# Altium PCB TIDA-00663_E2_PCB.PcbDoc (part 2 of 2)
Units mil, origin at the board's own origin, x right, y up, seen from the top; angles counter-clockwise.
Board outline 1968.5 x 1968.5 mil, 4 copper layers (Top Layer, Mid-Layer 1, Mid-Layer 2, Bottom Layer), stack 90 mil thick; 73 components, 52 nets, 290 pads, 111 vias.
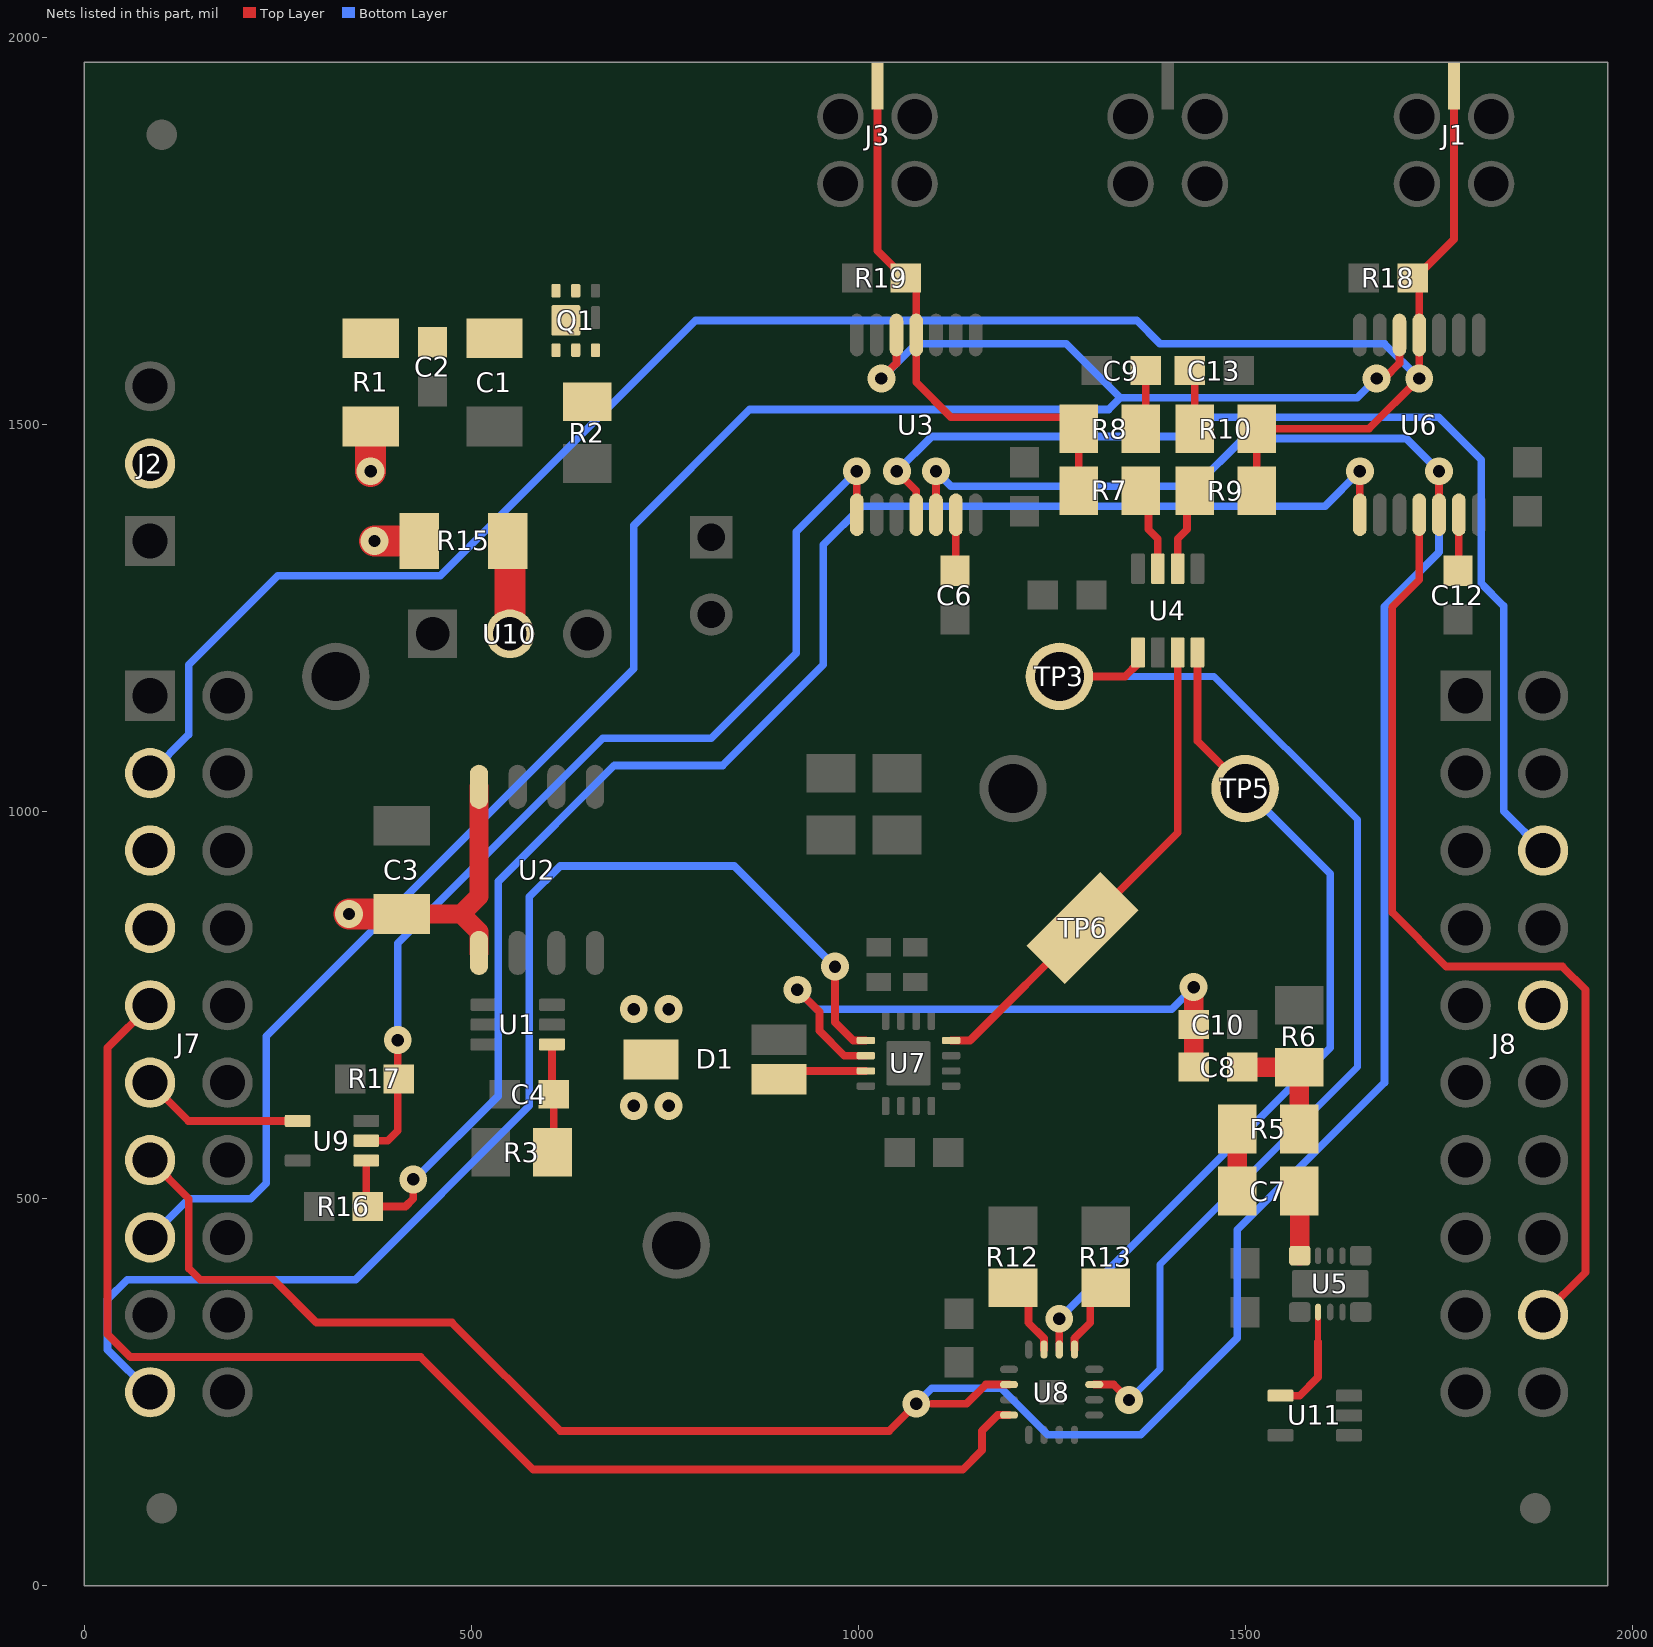
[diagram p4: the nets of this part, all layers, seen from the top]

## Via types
v1: diameter 36, hole 16, Top Layer to Bottom Layer, tented both sides, 84 vias
v2: diameter 19.68, hole 7.87, Top Layer to Bottom Layer, 25 vias
v3: diameter 19.68, hole 7.87, Top Layer to Bottom Layer, tented top, 1 vias
v4: diameter 36, hole 16, Top Layer to Bottom Layer, 1 vias

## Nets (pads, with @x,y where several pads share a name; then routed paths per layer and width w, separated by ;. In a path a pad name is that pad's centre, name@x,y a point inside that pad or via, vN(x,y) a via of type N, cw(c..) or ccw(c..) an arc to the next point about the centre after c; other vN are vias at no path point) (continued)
LASER_ON_THRESHOLD: TP3.1 U4.1 U8.11 | length 1469.7
  Top Layer w10: TP3.1@1300,1175 1345,1175 1361.61,1191.61 U4.1@1361.61,1205.87 ; U8.11@1305.12,259.84 1330.16,259.84 v1(1350,240)
  Bottom Layer w9: TP3.1@1260,1175 1460,1175 1645,990 1645,670 1390,415 1390,280 v1(1350,240)
NetC1_1: C1.1 C2.1 Q1.1 Q1.2 Q1.5 Q1.6 Q1.8 R1.1
NetC4_1: C4.1 R3.2 U1.1 | length 140.9
  Top Layer w10: C4.1@604.29,637.2 U1.1@604.29,699.41 ; R3.2@605,560 606.5,561.5 C4.1@606.5,635
  Top Layer w15: C4.1@604.29,637.2 C4.1@606.5,635
NetC6_1: C6.1 U3.13 | length 77.9
  Top Layer w10: C6.1@1125,1311.5 C6.1@1126.18,1312.68 ; C6.1@1126.18,1307.68 C6.1@1126.18,1312.68 ; U3.13@1126.18,1383.86 C6.1@1126.18,1312.68
NetC7_1: C7.1 R5.1 | length 80
  Top Layer w25: C7.1@1490,510 R5.1@1490,590
NetC7_2: C7.2 U5.13 U5.14 | length 83.8
  Top Layer w25: C7.2@1570,510 1570.63,509.37 U5.13@1570.63,426.42
NetC8_1: C8.1 R5.2 R6.1 | length 153.5
  Top Layer w25: C8.1@1496.5,670 R6.1@1570,670 R5.2@1570,590
NetC9_1: C9.1 R8.1 | length 77.7
  Top Layer w10: R8.1@1365,1495 1371.5,1501.5 C9.1@1371.5,1570
NetC12_1: C12.1 U6.13 | length 74.5
  Top Layer w10: C12.1@1775,1301.5 C12.1@1776.18,1302.68 ; C12.1@1775,1311.5 1776.18,1312.68 U6.13@1776.18,1383.86
NetC13_1: C13.1 R10.1 | length 77.7
  Top Layer w10: C13.1@1428.5,1570 1435,1563.5 R10.1@1435,1495
NetD1_3: D1.3 U7.15 | length 117.5
  Top Layer w10: D1.3@892.68,654.41 D1.3@893.43,655.16 ; D1.3@893.43,665.16 U7.15@1009.88,665.16
NetQ1_3: Q1.3 R2.2
NetR12_1: R12.1 U8.15 | length 96.5
  Top Layer w9: R12.1@1200,385 R12.1@1220,365
  Top Layer w10: R12.1@1220,365 1220,340 1240.16,319.84 U8.15@1240.16,305.12
NetR13_1: R13.1 U8.13 | length 96.6
  Top Layer w9: R13.1@1300,365 R13.1@1320,385
  Top Layer w10: U8.13@1279.53,305.12 1279.53,319.53 1300,340 R13.1@1300,365
NetR15_1: R15.1 U10.2 | length 121.2
  Top Layer w40: R15.1@547.09,1350 550,1347.09 U10.2@550,1230
NetTP6_1: TP6.1 U4.3 U7.8 | length 636.9
  Top Layer w10: U7.8@1120.12,704.53 1144.53,704.53 TP6.1@1290,850 1412.8,972.8 U4.3@1412.8,1205.87
NetU5_3: U5.3 U11.4 | length 142.6
  Top Layer w7.8: 1594.25,315 U5.3@1594.25,353.58
  Top Layer w10: U11.4@1545.71,245.59 1570.51,245.59 1594.25,269.33 1594.25,315
OPA_TEST_INPUT: C8.2 C10.1 U7.14 | length 777.2
  Top Layer w10: v1@923,770 v1(921.5,770) 950,741.5 950,717 982.16,684.84 U7.14@1009.88,684.84
  Top Layer w25: C8.2@1433.5,670 C10.1@1433.5,725 v1(1433.5,773.5)
  Bottom Layer w10: v1(921.5,770) 946.5,745 1405,745 v1(1433.5,773.5)
RST: J8.10
RX: J1.1 J7.3 R9.2 R10.2 R18.2 U6.4 | length 2679.2
  Top Layer w10: R9.2@1515,1415 R10.2@1515,1495 1660,1495 v1(1725,1560) U6.4@1725,1616.14 1725,1695 1770,1740 J1.1@1770,1937.5
  Bottom Layer w10: J7.3@85,1050 135,1100 135,1190 250,1305 460,1305 790,1635 1360,1635 1390,1605 1680,1605 v1(1725,1560)
RX_COMP: R9.1 U4.6 | length 110.1
  Top Layer w10: U4.6@1412.8,1314.13 1412.8,1352.8 1425,1365 1425,1405 R9.1@1435,1415
SPI_CLK_P1.3_BP7: J7.13 U3.12 U6.12 U8.2 | length 3853.7
  Top Layer w10: J7.13@85,550 135,500 135,410 149.65,395.35 244.65,395.35 300,340 475,340 615,200 1040,200 v1(1075,235) ; 1095,235 1140,235 1164.84,259.84 U8.2@1194.88,259.84 ; U3.12@1100.59,1383.86 v1(1100.59,1440) ; U6.12@1750.59,1383.86 v1(1750.59,1440)
  Bottom Layer w10: v1(1075,235) 1095,255 1185,255 1245,195 1365,195 1490,320 1490,460 1680,650 1680,1265 1750.59,1335.59 v1(1750.59,1440) 1708.22,1482.37 1497.37,1482.37 1435.62,1420.62 1119.97,1420.62 v1(1100.59,1440)
TDC_CLK: J7.15 U3.5 U6.5 | length 2759.1
  Top Layer w10: v1(1030,1560) 1049.41,1579.41 U3.5@1049.41,1616.14 ; v1(1670,1560) 1680,1560 1699.41,1579.41 U6.5@1699.41,1616.14
  Bottom Layer w10: J7.15@85,450 135,500 215,500 235,520 235,710 710,1185 710,1370 860,1520 1323.66,1520 1338.66,1535 ; v1(1030,1560) 1075,1605 1268.66,1605 1338.66,1535 ; v1(1670,1560) 1645,1535 1338.66,1535
TDC_INT: J7.11 U9.4 | length 221.2
  Top Layer w10: J7.11@85,650 134.41,600.59 U9.4@275.71,600.59 U9.4@285.71,600.59
TDC_RX_CS: J8.18 U6.11 | length 1262.6
  Top Layer w10: U6.11@1725,1383.86 1725,1300 1690,1265 1690,870 1760,800 1910,800 1940,770 1940,405 J8.18@1885,350
TDC_RX_INT: R16.1 U6.8 U9.1 | length 2059.5
  Top Layer w10: U9.1@364.29,549.41 364.29,492.2 R16.1@366.5,490 415,490 425,500 v1(425,525) ; U6.8@1648.23,1383.86 v1(1648.23,1440)
  Bottom Layer w10: v1(425,525) 427.17,525 535,632.83 535,910 685,1060 825,1060 955,1190 955,1345 1005,1395 1603.23,1395 v1(1648.23,1440)
TDC_TX_CS: J8.6 U3.11 | length 1411.4
  Top Layer w10: v1(1050,1440) 1075,1415 U3.11@1075,1383.86
  Bottom Layer w10: v1(1050,1440) 1095,1485 1415,1485 1440,1510 1750,1510 1805,1455 1805,1295 1834.13,1265.87 1834.13,1000.87 J8.6@1885,950
TDC_TX_INT: R17.1 U3.8 U9.2 | length 1287.7
  Top Layer w10: U9.2@364.29,575 391.91,575 405,588.09 v1(405,705) ; U3.8@998.23,1383.86 v1(998.23,1440)
  Bottom Layer w10: v1(405,705) 405,830 670,1095 810,1095 920,1205 920,1361.77 v1(998.23,1440) ; v1@994.11,1444.11 v1@998.23,1448.23
TPL0202_CS_EN_GPIO_BP5: J7.9 U8.4 | length 1729
  Top Layer w10: J7.9@85,750 30,695 30,325 59.65,295.35 434.65,295.35 580,150 1135,150 1160,175 1160,200 1180.47,220.47 U8.4@1194.88,220.47
TPROP_CALIBRATION_ENABLE_BP10_P3.6: J7.19 U7.13 | length 1648.4
  Top Layer w10: v1(970,800) 970,728 993.47,704.53 U7.13@1009.88,704.53
  Bottom Layer w10: J7.19@85,250 30,305 30,370 55.35,395.35 350.35,395.35 575,620 575,890 615,930 840,930 v1(970,800)
TX: J3.1 R7.2 R8.2 R19.2 U3.4 | length 718.1
  Top Layer w10: J3.1@1025,1937.5 1025,1725 1075,1675 U3.4@1075,1616.14 1075,1555 1120,1510 1270,1510 R8.2@1285,1495 R7.2@1285,1415
TX_COMP: R7.1 U4.7 | length 115.9
  Top Layer w10: R7.1@1365,1415 1375,1415 1375,1365 1387.2,1352.8 U4.7@1387.2,1314.13
UCA0RXD_P1.2_BP4: J7.7
UCA0TXD_P1.1_BP3: J7.5
VCC_LASER: C3.1 D1.1 J2.2 R1.2 R15.2 U2.1 U2.8 | length 494.4
  Top Layer w25: C3.1@410,867.91 487.09,867.91 ; U2.1@510,817.72 510,845 487.09,867.91 ; U2.8@510,1032.28 510,890.83 487.09,867.91
  Top Layer w40: v1(342.09,867.91) C3.1@410,867.91 ; v1(370,1440) R1.2@370,1497.91 ; v1(375,1350) R15.2@432.91,1350
  other v1: 710,620 755,620 710,745 755,745
VOUTN_DIGITAL: TP5.1 U4.4 U8.14 | length 1116.9
  Top Layer w10: U8.14@1259.84,305.12 v1(1259.84,344.84) ; U4.4@1438.39,1205.87 1438.39,1091.61 TP5.1@1500,1030
  Bottom Layer w10: v1(1259.84,344.84) 1610,695 1610,920 TP5.1@1500,1030
pads on no net: D1.2 FID1.1 FID2.1 FID3.1 J7.6 J7.8 J7.10 J7.12 J7.14 J7.16 J7.18 J7.20 J8.1 J8.3 J8.5 J8.7 J8.9 J8.11 J8.13 J8.15 J8.17 J8.19 U3.2 U3.6 U5.0 U5.1@1578.5,353.58 U5.1@1578.5,426.42 U5.1@1641.5,353.58 U5.1@1641.5,426.42 U5.2@1570.63,360.47 U5.2@1570.63,419.53 U5.2@1649.37,360.47 U5.2@1649.37,419.53 U5.6 U5.7 U5.8 U5.9 U5.10 U5.12 U6.2 U6.6 U7.5 U7.16 U8.5 U8.6 U8.8 U8.9 U8.16

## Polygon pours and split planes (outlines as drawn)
GND on Top Layer "Top Layer-No Net 1" (solid, remove dead copper, pour order 6): 1090,995 885,995 885,895 1140,895 1140,965 1110,995
LASER_ON on Top Layer "Top Layer-No Net" (solid, remove dead copper, pour order 4): 590,1250 590,1190 755,1025 1105,1025 1175,955 1230,955 1275,1000 1275,1055 1215,1115 1025,1115 835,1305 590,1305
NetC1_1 on Top Layer "Top Layer-No Net 2" (solid, remove dead copper, pour order 8): 330,1710 640,1710 640,1585 330,1585
NetQ1_3 on Top Layer "Top Layer-No Net 3" (solid, remove dead copper, pour order 10): 655,1605 655,1590 615,1550 615,1505 705,1505 705,1605
ALIGNEMENT_MODE_SUPPLY on Top Layer "PLANE_D2" (solid, remove dead copper, pour order 12): 655,1625 725,1625 745,1605 745,1355 760,1340 860,1340 875,1355 875,1650 815,1710 655,1710
VCC_LASER on Top Layer "Top Layer-No Net 5" (solid, remove dead copper, pour order 14): 690,765 690,600 775,600 775,765
GND on Top Layer "Top Layer-No Net 6" (solid, remove dead copper, pour order 16): 1040,790 1040,718 1010,718 1010,790
BP_3.3V on Top Layer "Top Layer-No Net 7" (solid, remove dead copper, pour order 18): 1058,790 1058,768 1050,760 1050,718 1100,718 1100,757.5 1089,768.5 1089,790
GND on Mid-Layer 1 "Mid-Layer 1-No Net" (solid, remove dead copper, pour order 22): 0,1968.5 1968.5,1968.5 1968.5,0 0,0
VCC_LASER on Mid-Layer 2 "Mid-Layer 2-No Net 1" (solid, remove dead copper, pour order 26): 20.39,1948.11 20.39,1271.5 21.89,1270 210,1270 210,1268.96 260,1218.96 260,850 310,800 550,800 600,750 600,600 650,550 750,550 800,600 800,1950
BP_3.3V on Mid-Layer 2 "Mid-Layer 2-No Net 2" (solid, remove dead copper, pour order 28): 20,1250 200,1250 240,1210 240,840 300,780 540,780 580,740 580,590 640,530 760,530 820,590 820,1950 1950,1950 1950,20 20,20

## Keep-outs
Keep-Out Layer:
  text ".Layer_Name" at 577,-858.49 h60

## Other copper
Top Layer:
  text ".Layer_Name" at 577,-858.49 h60
Mid-Layer 1:
  text ".Layer_Name" at 577,-858.49 h60
Mid-Layer 2:
  text ".Layer_Name" at 577,-858.49 h60
Bottom Layer:
  text ".Layer_Name" at 577,-858.49 h60

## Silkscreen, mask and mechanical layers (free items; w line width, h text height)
Top Overlay:
  lines w10: 50,1100 1905,1100
  text "TX" at 610,1320 h40
  text "BP1" at 35,1210 h40
  text "BP20" at 1815,1205 h37
  text "RX" at 785,740 h40
  text "BP10" at 25,160 h40
  text "BP11" at 1825,160 h40
  text ".PRJ_Title" at 245,40 h100
  text ".Layer_Name" at 577,-858.49 h60
Bottom Overlay:
  text ".Layer_Name" at 577,-858.49 h60
Top Paste:
  text ".Layer_Name" at 577,-858.49 h60
Bottom Paste:
  text ".Layer_Name" at 577,-858.49 h60
Top Solder:
  text ".Layer_Name" at 577,-858.49 h60
  text ".Layer_Name" at 577,-858.49 h60
Bottom Solder:
  text ".Layer_Name" at 577,-858.49 h60
Drill Guide:
  text ".Layer_Name" at 577,-858.49 h60
M1 Board Outline:
  the board outline again, w10
  text ".Layer_Name" at 577,-858.49 h60
M2 Board Dimensions:
  rectangle: 0,-275 125,-150
  rectangle: 125,-400 500,-275
  lines w7: 0,-275 1000,-275 ; 125,-400 125,-150 ; 250,-400 250,-150 ; 500,-400 500,-150 ; 750,-400 750,-150 ; 0,-400 1000,-400 1000,-150 0,-150 0,-400
  text ".Layer_Name" at 577,-858.49 h60
M3 3D STEP Top:
  text ".Layer_Name" at 577,-858.49 h60
M4 3D STEP Bottom:
  text ".Layer_Name" at 577,-858.49 h60
M5 Assembly Top:
  lines w10: -292,-930.17 6308,-930.17 ; -292,-726.83 6310,-726.83 ; -292,-523.5 -292,-1133.5 3713,-1133.5 6310,-1133.5 6310,-523.5 -291.5,-523.5 -291.5,-1133.5 1284,-1133.5 ; 2173,-1133.5 2173,-523.5 ; 3440,-726.83 3440,-523.5 ; 4280,-726.83 4280,-523.5 ; 4902,-1140 4902,-937.17
  text "COMPONENTS MARKED 'DNP' SHOULD NOT BE POPULATED." at 1153.5,-318.5 h60
  text "ASSEMBLY VARIANT:" at 1153,-434 h60
  text ".VariantName" at 2189,-434 h60
  text "PCB VIEWED FROM TOP SIDE" at -228.5,-655.67 h60
  text "BOARD #:" at 2248,-655.67 h60
  text ".PRJ_Number" at 2793.5,-655.67 h60
  text "REV:" at 3638,-655.67 h60
  text ".PCB_Rev" at 3929.5,-655.67 h60
  text "SVN REV:" at 4476,-655.67 h60
  text ".VersionControl_RevNumber" at 4982,-655.67 h60
  text "TID #:" at 2248,-859 h60
  text ".TID" at 2793.5,-859 h60
  text "PLOT NAME =" at -228.5,-1064.34 h60
  text ".plot_File_Name" at 577,-1064.34 h60
  text "GENERATED    :" at 2250,-1064.34 h60
  text ".Print_Date" at 3119.5,-1064.34 h60
  text ".Print_Time" at 3848.5,-1064.34 h60
  text "TEXAS INSTRUMENTS" at 5113,-1064.34 h60
M6 Assembly Bottom:
  lines w10: -292.5,-727.33 6309.5,-727.33 ; -290.5,-930.67 6309.5,-930.67 ; 1115.5,-1140.5 1115.5,-937.67 ; 1737.5,-727.33 1737.5,-524 ; 2577.5,-727.33 2577.5,-524 ; 3844.5,-1134 3844.5,-524 ; 4733.5,-1134 6309,-1134 6309,-524 -292.5,-524 -292.5,-1134 2304.5,-1134 6309.5,-1134 6309.5,-524
  text "COMPONENTS MARKED 'DNP' SHOULD NOT BE POPULATED." at 6102,-318 h60
  text ".VariantName" at 5058,-434 h60
  text "ASSEMBLY VARIANT:" at 6097,-434 h60
  text ".VersionControl_RevNumber" at 1035.5,-656.17 h60
  text "SVN REV:" at 1541.5,-656.17 h60
  text ".PCB_Rev" at 2088,-656.17 h60
  text "REV:" at 2379.5,-656.17 h60
  text ".PRJ_Number" at 3224,-656.17 h60
  text "BOARD #:" at 3769.5,-656.17 h60
  text "PCB VIEWED FROM BOTTOM SIDE" at 6246,-656.17 h60
  text ".TID" at 3224,-859.5 h60
  text "TID #:" at 3769.5,-859.5 h60
  text "TEXAS INSTRUMENTS" at 904.5,-1064.84 h60
  text ".Print_Time" at 2169,-1064.84 h60
  text ".Print_Date" at 2898,-1064.84 h60
  text "GENERATED    :" at 3767.5,-1064.84 h60
  text ".plot_File_Name" at 5440.5,-1064.84 h60
  text "PLOT NAME =" at 6246,-1064.84 h60
M9 Title Sheet:
  drawing of 57 lines, arcs and shapes, not listed
  text "1" at 739.84,8036.5 h70
  text "2" at 3235.5,8036.5 h70
  text "3" at 5724.84,8036.5 h70
  text "4" at 8231.51,8036.5 h70
  text "5" at 10730.5,8036.5 h70
  text "6" at 13235.5,8036.5 h70
  text "A" at -416.5,6893.5 h70
  text "A" at 14383.5,6893.5 h70
  text "B" at -416.5,4513.5 h70
  text "B" at 14383.5,4513.5 h70
  text "C" at -416.5,2138.5 h70
  text "C" at 14383.5,2138.5 h70
  text "PROJECT TITLE:" at 11343.5,277.5 h45
  text ".PRJ_Title" at 11393.5,144.17 h70
  text "DESIGNED FOR:" at 11343.5,-23.5 h45
  text ".PRJ_Customer" at 11393.5,-163.5 h70
  text "D" at -416.5,-231.5 h70
  text "D" at 14383.5,-231.5 h70
  text "FILE NAME:" at 11343.5,-323.5 h45
  text ".PCB_File_Name_No_Path" at 11393.5,-443.5 h70
  text "Texas Instruments (TI) and/or its licensors do not warrant the accuracy or completeness of this specification" at 6374,-605.34 h45
  text "ENGINEER:" at 11343.5,-613.5 h45
  text "LAYOUT BY:" at 12848.5,-613.5 h45
  text "or any information contained therein. TI and/or its licensors do not warrant that this design will meet" at 6329.01,-718 h45
  text ".PRJ_Engineer" at 11393.5,-768.49 h70
  text ".PCB_Layout" at 12899,-768.49 h70
  text "the specifications, will be suitable for your application or fit for any particular purpose, or will operate in" at 6329.01,-830.67 h45
  text ".Layer_Name" at 577,-858.49 h60
  text "ALTIUM DESIGNER VERSION:" at 12848.5,-923.5 h45
  text "an implementation. TI and/or its licensors do not warrant that the design is production worthy. You should" at 6329.01,-943.33 h45
  text "completely validate and test your design implementation to confirm the system functionality for your application." at 6374,-1056 h45
  text ".print_Scale" at 11393.5,-1056.83 h70
  text ".Application_BuildNumber" at 12899,-1056.83 h70
  text "1" at 739.84,-1263.5 h70
  text "2" at 3235.5,-1263.5 h70
  text "3" at 5724.84,-1263.5 h70
  text "4" at 8231.51,-1263.5 h70
  text "5" at 10730.5,-1263.5 h70
  text "6" at 13235.5,-1263.5 h70
M10 Fab Notes:
  drawing of 173 lines, arcs and shapes, not listed
  text "DESIGN INFORMATION" at 12378.02,6201 h60
  text "MIN. TRACK WIDTH:" at 11733.46,6021 h60
  text "8" at 12829.7,6021 h60
  text "MIL" at 12984.46,6021 h60
  text "MIN. CLEARANCE:" at 11733.46,5889 h60
  text "0.2" at 12769.7,5889 h60
  text "mm" at 12984.46,5889 h60
  text "MIN. VIA PAD SIZE:" at 11733.46,5757 h60
  text "24" at 12799.71,5757 h60
  text "MIL" at 12984.46,5757 h60
  text "0.05mm (2MIL)" at 12428.46,5615.29 h60
  text "MINIMUM ANNULAR RING" at 11404.23,5611 h60
  text "EXTERNAL" at 13136.46,5611 h60
  text "PER" at 11604.23,5493 h60
  text "IPC-D-275 CLASS 2 LEVEL C" at 11824.23,5493 h60
  text "MIL, HOLES" at 13312.46,5380.71 h60
  text "+/-" at 12920,5380 h60
  text "+/-" at 13774,5380 h60
  text "REGISTRATION TOLERANCES:" at 11404.23,5375 h60
  text "METAL" at 12604,5375 h60
  text "5" at 13180.2,5375 h60
  text "3" at 14013.2,5375 h60
  text "MIL" at 14129.46,5375 h60
  text "+/-" at 13774,5262 h60
  text "HOLE SIZE TOLERANCE (UNLESS OTHERWISE SPECIFIED):" at 11404.23,5257 h60
  text "3" at 14013.2,5257 h60
  text "MIL" at 14129.46,5257 h60
  text "MATERIAL:" at 11329.46,5047.54 h60
  text "FR-4 High Tg" at 12315.9,4907.21 h60
  text "FR-408" at 11750.46,4898.64 h60
  text "OTHER" at 13238.46,4898.64 h60
  text "X" at 12161,4895 h60
  text "62 MIL (1.6mm) +/-10%" at 12070.56,4735.92 h60
  text "THICKNESS:" at 11404.23,4731.64 h60
  text "X" at 11942.4,4731.64 h60
  text "OTHER" at 13355.46,4731.64 h60
  text "TOLERANCE:" at 11404.23,4573.64 h60
  text "X" at 12243.53,4573.64 h60
  text "ANSI IPC-6012 TYPE 3 CLASS 2" at 12430.48,4573.64 h60
  text "OTHER +/-" at 12430.46,4417.64 h60
  text "BOW & TWIST:" at 11404.23,4260.64 h60
  text "X" at 12243.53,4260.64 h60
  text "ANSI IPC-6012 TYPE 3 CLASS 2" at 12430.48,4260.64 h60
  text "OTHER +/-" at 12430.46,4102.13 h60
  text "DRILLING:" at 11329.46,3963.64 h60
  text "REFERENCE:" at 11404.23,3846.64 h60
  text "X" at 12052.46,3846.64 h60
  text "AS SHOWN" at 12239.46,3846.64 h60
  text "X" at 12953.46,3846.64 h60
  text "NC_DRILL FILES" at 13090.46,3846.64 h60
  text "PTH MIN COPPER THICKNESS:" at 11404.23,3688.64 h60
  text "X" at 12754.46,3688.64 h60
  text "1MIL" at 12891.46,3688.64 h60
  text "OTHER" at 13388.46,3688.64 h60
  text "BOARD FINISH:" at 11329.46,3529.64 h60
  text "SILKSCREEN:" at 11484.68,3411.64 h60
  text "X" at 12433.46,3411.64 h60
  text "TOP" at 12559.46,3411.64 h60
  text "X" at 12943.46,3411.64 h60
  text "BOTTOM" at 13070.46,3411.64 h60
  text "SILKSCREEN COLOR:" at 11484.68,3244.64 h60
  text "X" at 12432.42,3244.64 h60
  text "WHITE" at 12559.46,3244.64 h60
  text "OTHER" at 13070.46,3244.64 h60
  text "X" at 12563.42,3085.44 h60
  text "GREEN" at 12690.46,3085.44 h60
  text "OTHER" at 13308.46,3085.44 h60
  text "SOLDER RESIST COLOR:" at 11484.68,3074.64 h60
  text "X" at 12563.42,2915.44 h60
  text "MATTE" at 12690.46,2915.44 h60
  text "SEMI-GLOSS" at 13308,2914.8 h60
  text "IMMERSION GOLD (ENIG)" at 12390.46,2726.92 h60
  text "ENEPIG" at 13728,2723.64 h60
  text "SURFACE FINISH:" at 11329.46,2722.64 h60
  text "X" at 12203.51,2722.64 h60
  text "IMM. TIN/SILVER OR EQUIV" at 11659,2565.64 h60
  text "OTHER" at 13090.46,2565.64 h60
  text "ARRAY/PANEL:" at 11329.46,2386.64 h60
  text "CUT AND TRIM PER M1 BOARD OUTLINE" at 12390.46,2382.35 h60
  text "N.C. ROUTE" at 12390.46,2230.64 h60
  text "X" at 13069.46,2230.64 h60
  text "V. SCORE" at 13256.46,2230.64 h60
  text "CERTIFICATION:" at 11329.46,2093.64 h60
  text "MATERIALS AND WORKMANSHIP FOR ALL PCBS" at 12054.46,2093.64 h60
  text "TO MEET OR EXCEED THE REQUIREMENTS OF:" at 12054.46,1995.64 h60
  text "X" at 11680.96,1859.13 h60
  text "ANSI IPC-A-600F CLASS ->" at 11819.96,1859.13 h60
  text "X" at 13459.02,1859.13 h60
  text "2" at 13577.96,1859.14 h60
  text "1" at 13262.96,1857.64 h60
  text "3" at 13931.96,1857.64 h60
  text "X" at 12495.02,1699.64 h60
  text "RoHS" at 12631.96,1699.64 h60
  text "OTHER" at 13276.36,1699.64 h60
  text "PER ORDER" at 13673.42,1699.64 h60
  text "ALL BOARDS MUST MEET OR EXCEED UL94-V0 REQUIREMENTS." at 11357,1534 h60
  text "PCB MUST BEAR THE UL94V-0 UL REGISTERED MATERIAL ID NUMBER" at 11357,1414 h60
  text "ADDITIONAL REQUIREMENTS:" at 11329.46,1240.64 h60
  text "MICROSECTION:" at 11404.23,1125.64 h60
  text "YES" at 12309.96,1125.64 h60
  text "REQUIRED" at 13171.46,969.49 h60
  text "BARE BOARD ELEC. TEST:" at 11404.23,966.64 h60
  text "NONE" at 12709.96,966.64 h60
  text "X" at 13044.46,966.64 h60
  text "PER ORDER" at 13763.46,966.64 h60
  text ".Layer_Name" at 577,-858.49 h60
M11 Gerber Information:
  lines w10: -292,-930.17 6308,-930.17 ; -292,-726.83 6310,-726.83 ; -292,-523.5 -292,-1133.5 3713,-1133.5 6310,-1133.5 6310,-523.5 -291.5,-523.5 -291.5,-1133.5 1284,-1133.5 ; 2173,-1133.5 2173,-523.5 ; 3440,-726.83 3440,-523.5 ; 4280,-726.83 4280,-523.5 ; 4902,-1140 4902,-937.17
  text "ALL ARTWORK VIEWED FROM TOP SIDE" at -228.5,-655.67 h60
  text "BOARD #:" at 2248,-655.67 h60
  text ".PRJ_Number" at 2793.5,-655.67 h60
  text "REV:" at 3638,-655.67 h60
  text ".PCB_Rev" at 3929.5,-655.67 h60
  text "SVN REV:" at 4476,-655.67 h60
  text ".VersionControl_RevNumber" at 4982,-655.67 h60
  text "LAYER NAME =" at -228.5,-858.49 h60
  text "TID #:" at 2248,-859 h60
  text ".TID" at 2793.5,-859 h60
  text "PLOT NAME =" at -228.5,-1064.34 h60
  text ".plot_File_Name" at 577,-1064.34 h60
  text "GENERATED    :" at 2250,-1064.34 h60
  text ".Print_Date" at 3119.5,-1064.34 h60
  text ".Print_Time" at 3848.5,-1064.34 h60
  text "TEXAS INSTRUMENTS" at 5113,-1064.34 h60
M12 Stackup:
  drawing of 295 lines, arcs and shapes, not listed
  text "Layer" at 9777.5,7795.5 h60
  text "Name" at 10187.41,7795.5 h60
  text "Material" at 11117.16,7795.5 h60
  text "Thickness" at 11976.92,7795.5 h60
  text "Constant" at 12626.76,7795.5 h60
  text "Board Layer Stack" at 13196.62,7795.5 h60
  text "1" at 9777.5,7675.5 h60
  text "Top Overlay" at 10187.41,7675.5 h60
  text "2" at 9777.5,7555.5 h60
  text "Top Solder" at 10187.41,7555.5 h60
  text "Solder Resist" at 11117.16,7555.5 h60
  text "0.40mil" at 11976.92,7555.5 h60
  text "3.5" at 12626.76,7555.5 h60
  text "3" at 9777.5,7435.5 h60
  text "Top Layer" at 10187.41,7435.5 h60
  text "Copper" at 11117.16,7435.5 h60
  text "1.40mil" at 11976.92,7435.5 h60
  text "4" at 9777.5,7315.5 h60
  text "Dielectric1" at 10187.41,7315.5 h60
  text "FR-4" at 11117.16,7315.5 h60
  text "59.20mil" at 11976.92,7315.5 h60
  text "4.8" at 12626.76,7315.5 h60
  text "5" at 9777.5,7195.5 h60
  text "Mid-Layer 1" at 10187.41,7195.5 h60
  text "Copper" at 11117.16,7195.5 h60
  text "1.40mil" at 11976.92,7195.5 h60
  text "6" at 9777.5,7075.5 h60
  text "Dielectric3" at 10187.41,7075.5 h60
  text "FR-4" at 11117.16,7075.5 h60
  text "12.60mil" at 11976.92,7075.5 h60
  text "4.8" at 12626.76,7075.5 h60
  text "7" at 9777.5,6955.5 h60
  text "Mid-Layer 2" at 10187.41,6955.5 h60
  text "Copper" at 11117.16,6955.5 h60
  text "1.40mil" at 11976.92,6955.5 h60
  text "8" at 9777.5,6835.5 h60
  text "Dielectric2" at 10187.41,6835.5 h60
  text "FR-4" at 11117.16,6835.5 h60
  text "12.60mil" at 11976.92,6835.5 h60
  text "4.8" at 12626.76,6835.5 h60
  text "9" at 9777.5,6715.5 h60
  text "Bottom Layer" at 10187.41,6715.5 h60
  text "Copper" at 11117.16,6715.5 h60
  text "1.40mil" at 11976.92,6715.5 h60
  text "10" at 9777.5,6595.5 h60
  text "Bottom Solder" at 10187.41,6595.5 h60
  text "Solder Resist" at 11117.16,6595.5 h60
  text "0.40mil" at 11976.92,6595.5 h60
  text "3.5" at 12626.76,6595.5 h60
  text "11" at 9777.5,6475.5 h60
  text "Bottom Overlay" at 10187.41,6475.5 h60
  text ".Layer_Name" at 577,-858.49 h60
M13 Component Bodies Top:
  text ".Layer_Name" at 577,-858.49 h60
M14 Component Bodies Bottom:
  text ".Layer_Name" at 577,-858.49 h60
M15 Courtyards Top:
  text ".Layer_Name" at 577,-858.49 h60
M16 Courtyards Bottom:
  text ".Layer_Name" at 577,-858.49 h60
Drill Drawing:
  circle w10: c3153.82,1236.02 r27.67
  lines w10: 3126.16,461.35 3181.49,461.35 3181.49,516.68 3126.16,516.68 3126.16,461.35 ; 3126.16,585.85 3181.49,585.85 3181.49,641.18 3126.16,641.18 3126.16,585.85 ; 3126.16,710.35 3153.82,724.18 3181.49,710.35 3167.66,738.02 3181.49,765.68 3153.82,751.85 3126.16,765.68 3139.99,738.02 3126.16,710.35 ; 3126.16,848.68 3139.99,848.68 3153.82,834.85 3167.66,848.68 3181.49,848.68 3167.66,862.52 3181.49,876.35 3167.66,876.35 3153.82,890.18 3139.99,876.35 3126.16,876.35 3139.99,862.52 3126.16,848.68 ; 3126.16,1014.68 3181.49,1014.68 3153.82,959.35 3126.16,1014.68 ; 3126.16,1097.68 3139.99,1097.68 3139.99,1083.85 3167.66,1083.85 3167.66,1097.68 3181.49,1097.68 3181.49,1125.35 3167.66,1125.35 3167.66,1139.18 3139.99,1139.18 3139.99,1125.35 3126.16,1125.35 3126.16,1097.68 ; 3137.22,472.42 3170.43,472.42 3170.43,505.62 3137.22,505.62 3137.22,472.42 ; 3137.22,721.42 3153.82,729.72 3170.43,721.42 3162.12,738.02 3170.43,754.62 3153.82,746.32 3137.22,754.62 3145.53,738.02 3137.22,721.42 ; 3137.22,854.22 3145.53,854.22 3153.82,845.92 3162.12,854.22 3170.43,854.22 3162.12,862.52 3170.43,870.82 3162.12,870.82 3153.82,879.12 3145.53,870.82 3137.22,870.82 3145.53,862.52 3137.22,854.22 ; 3137.22,1103.22 3145.53,1103.22 3145.53,1094.92 3162.12,1094.92 3162.12,1103.22 3170.43,1103.22 3170.43,1119.82 3162.12,1119.82 3162.12,1128.12 3145.53,1128.12 3145.53,1119.82 3137.22,1119.82 3137.22,1103.22
  lines w12: 3076,424 5054.44,424 ; 3076,1295.5 5054.44,1295.5 ; 3414.01,299.5 3414.01,1420 ; 3746.17,299.5 3746.17,1420 ; 4382.65,299.5 4382.65,1420 ; 4641.85,299.5 4641.85,1420 ; 3076,299.5 5054.44,299.5 5054.44,1420 3076,1420 3076,299.5
  text "Symbol" at 3150.7,1332.85 h72
  text "Quantity" at 3451.36,1332.85 h72
  text "Finished Hole Size" at 3783.52,1332.85 h72
  text "Plated" at 4420,1332.85 h72
  text "Hole Type" at 4679.2,1332.85 h72
  text "26" at 3451.36,1208.35 h60
  text "7.87mil (0.200mm)" at 3783.52,1208.35 h60
  text "PTH" at 4420,1208.35 h60
  text "Round" at 4679.2,1208.35 h60
  text "85" at 3451.36,1083.85 h60
  text "16.00mil (0.406mm)" at 3783.52,1083.85 h60
  text "PTH" at 4420,1083.85 h60
  text "Round" at 4679.2,1083.85 h60
  text "2" at 3451.36,959.35 h60
  text "35.43mil (0.900mm)" at 3783.52,959.35 h60
  text "PTH" at 4420,959.35 h60
  text "Round" at 4679.2,959.35 h60
  text "3" at 3451.36,834.85 h60
  text "43.31mil (1.100mm)" at 3783.52,834.85 h60
  text "PTH" at 4420,834.85 h60
  text "Round" at 4679.2,834.85 h60
  text "12" at 3451.36,710.35 h60
  text "45.00mil (1.143mm)" at 3783.52,710.35 h60
  text "PTH" at 4420,710.35 h60
  text "Round" at 4679.2,710.35 h60
  text "43" at 3451.36,585.85 h60
  text "45.28mil (1.150mm)" at 3783.52,585.85 h60
  text "PTH" at 4420,585.85 h60
  text "Round" at 4679.2,585.85 h60
  text "5" at 3451.36,461.35 h60
  text "63.00mil (1.600mm)" at 3783.52,461.35 h60
  text "PTH" at 4420,461.35 h60
  text "Round" at 4679.2,461.35 h60
  text "176 Total" at 3451.36,336.85 h60
  text ".Layer_Name" at 577,-858.49 h60
M17 Embedded Cavity:
  text ".Layer_Name" at 577,-858.49 h60
M18 Embedded Assembly:
  text ".Layer_Name" at 577,-858.49 h60
M19 Embedded Keepout:
  text ".Layer_Name" at 577,-858.49 h60

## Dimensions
0,0 to 0,1968.5 on M2 Board Dimensions
0,0 to 1968.5,0 on M2 Board Dimensions
0,-400 to 1000,-400 on M2 Board Dimensions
